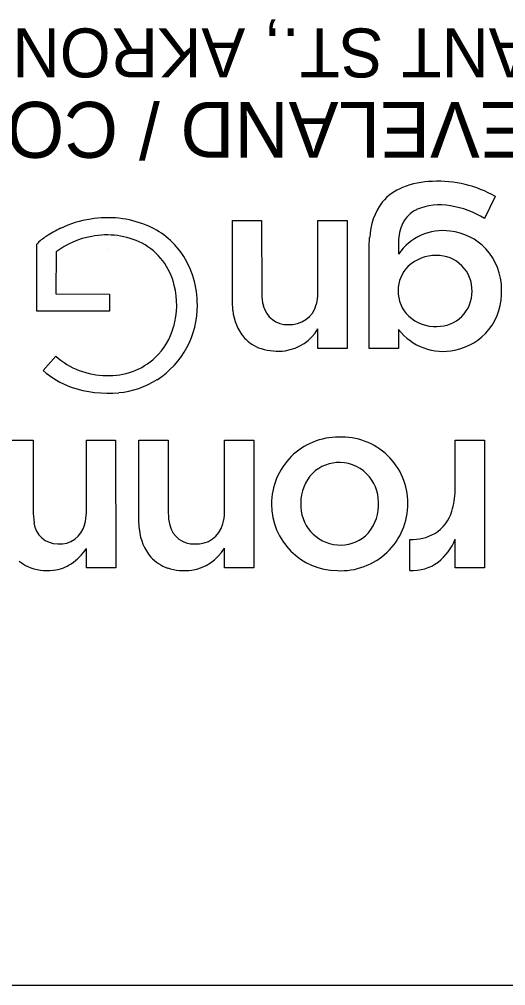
# Model space of a CAD drawing. Extents: x 2392589 to 2394670, y 184794 to 185659.
# Drawn here: x 2392957.49 to 2392967.39, y 185619.17 to 185638.86 of the extents above; entities that cross this region are included whole.
import ezdxf

# ---------------------------------------------------------------- set-up
doc = ezdxf.new("R2010")
doc.units = 0
doc.layers.add('MD_P_Surface_Asphalt_Concrete_Surface_Course', color=7, linetype='Continuous')
doc.layers.add('MD_P_Surface_Finished_Grade_Seeded', color=7, linetype='Continuous')

msp = doc.modelspace()

# ---------------------------------------------------------------- linework, layer by layer
at = {"layer": 'MD_P_Surface_Asphalt_Concrete_Surface_Course'}
for p, q in [((2392967.181, 185635.244), (2392966.96, 185634.797)), ((2392961.826, 185633.099), (2392961.826, 185634.756)), ((2392961.826, 185634.756), (2392962.422, 185634.756)), ((2392962.422, 185634.756), (2392962.423, 185633.269)), ((2392963.568, 185634.755), (2392964.164, 185634.756)), ((2392963.568, 185633.286), (2392963.568, 185634.755)), ((2392964.164, 185634.756), (2392964.166, 185632.15)), ((2392964.615, 185634.22), (2392964.622, 185634.411)), ((2392965.208, 185634.325), (2392965.207, 185634.07)), ((2392957.842, 185632.909), (2392957.841, 185634.276)), ((2392958.234, 185634.12), (2392958.231, 185633.262)), ((2392959.279, 185634.173), (2392959.279, 185634.173)), ((2392964.615, 185632.15), (2392964.615, 185634.22)), ((2392958.231, 185633.262), (2392959.324, 185633.259)), ((2392959.324, 185633.259), (2392959.324, 185632.909)), ((2392961.835, 185632.929), (2392961.826, 185633.099)), ((2392959.324, 185632.909), (2392957.842, 185632.909)), ((2392963.569, 185632.15), (2392963.568, 185632.552)), ((2392965.212, 185632.54), (2392965.212, 185632.15)), ((2392964.166, 185632.15), (2392963.569, 185632.15)), ((2392965.212, 185632.15), (2392964.615, 185632.15)), ((2392957.97, 185631.7), (2392958.231, 185631.995)), ((2392957.17, 185630.287), (2392957.766, 185630.287)), ((2392957.766, 185630.287), (2392957.766, 185628.79)), ((2392958.852, 185628.814), (2392958.852, 185630.287)), ((2392958.852, 185630.287), (2392959.448, 185630.287)), ((2392959.448, 185630.287), (2392959.449, 185627.681)), ((2392959.923, 185628.63), (2392959.923, 185630.287)), ((2392959.923, 185630.287), (2392960.519, 185630.287)), ((2392960.519, 185630.287), (2392960.52, 185628.8)), ((2392961.665, 185630.286), (2392962.26, 185630.287)), ((2392961.665, 185628.817), (2392961.665, 185630.286)), ((2392962.26, 185630.287), (2392962.262, 185627.681)), ((2392966.363, 185629.255), (2392966.365, 185630.287)), ((2392966.365, 185630.287), (2392966.961, 185630.286)), ((2392966.961, 185630.286), (2392966.961, 185627.681)), ((2392957.766, 185628.79), (2392957.785, 185628.601)), ((2392959.932, 185628.46), (2392959.923, 185628.63)), ((2392965.441, 185627.632), (2392965.441, 185628.263)), ((2392966.364, 185627.681), (2392966.364, 185628.267)), ((2392958.852, 185627.681), (2392958.852, 185628.076)), ((2392961.666, 185627.681), (2392961.665, 185628.083)), ((2392959.449, 185627.681), (2392958.852, 185627.681)), ((2392962.262, 185627.681), (2392961.666, 185627.681)), ((2392966.961, 185627.681), (2392966.364, 185627.681))]:
    msp.add_line(p, q, dxfattribs=at)
for points in [[(2392967.181, 185635.244), (2392966.96, 185634.797)], [(2392961.835, 185632.929), (2392961.826, 185633.099), (2392961.826, 185634.756), (2392962.422, 185634.756), (2392962.423, 185633.269)], [(2392963.568, 185633.286), (2392963.568, 185634.755), (2392964.164, 185634.756), (2392964.166, 185632.15)], [(2392965.212, 185632.54), (2392965.212, 185632.15), (2392964.615, 185632.15), (2392964.615, 185634.22), (2392964.622, 185634.411)], [(2392965.208, 185634.325), (2392965.207, 185634.07)], [(2392958.234, 185634.12), (2392958.231, 185633.262), (2392959.324, 185633.259), (2392959.324, 185632.909), (2392957.842, 185632.909), (2392957.841, 185634.276)], [(2392964.166, 185632.15), (2392963.569, 185632.15), (2392963.568, 185632.552)], [(2392957.97, 185631.7), (2392958.231, 185631.995)], [(2392957.169, 185628.816), (2392957.17, 185630.287), (2392957.766, 185630.287), (2392957.766, 185628.79), (2392957.785, 185628.601)], [(2392958.852, 185628.814), (2392958.852, 185630.287), (2392959.448, 185630.287), (2392959.449, 185627.681)], [(2392959.932, 185628.46), (2392959.923, 185628.63), (2392959.923, 185630.287), (2392960.519, 185630.287), (2392960.52, 185628.8)], [(2392961.665, 185628.817), (2392961.665, 185630.286), (2392962.26, 185630.287), (2392962.262, 185627.681)], [(2392966.363, 185629.255), (2392966.365, 185630.287), (2392966.961, 185630.286), (2392966.961, 185627.681)], [(2392965.441, 185627.632), (2392965.441, 185628.263)], [(2392966.961, 185627.681), (2392966.364, 185627.681), (2392966.364, 185628.267)], [(2392959.449, 185627.681), (2392958.852, 185627.681), (2392958.852, 185628.076)], [(2392962.262, 185627.681), (2392961.666, 185627.681), (2392961.665, 185628.083)]]:
    msp.add_lwpolyline(points, dxfattribs=at)
for centre, radius, start, end in [((2392965.937, 185633.786), 1.767, 91.1514, 111.3627), ((2392965.937, 185633.786), 1.767, 91.1514, 111.3627), ((2392966.031, 185633.28), 2.277, 59.6388, 93.26), ((2392966.031, 185633.28), 2.277, 59.6388, 93.26), ((2392965.672, 185634.476), 1.028, 111.6075, 140.5577), ((2392965.672, 185634.476), 1.028, 111.6075, 140.5577), ((2392965.922, 185634.354), 1.301, 143.4034, 177.4906), ((2392965.922, 185634.354), 1.301, 143.4034, 177.4906), ((2392965.848, 185634.425), 0.617, 116.2681, 153.803), ((2392965.848, 185634.425), 0.617, 116.2681, 153.803), ((2392966.049, 185633.886), 1.191, 79.3073, 113.4307), ((2392966.049, 185633.886), 1.191, 79.3073, 113.4307), ((2392966.012, 185633.32), 1.754, 57.3149, 81.5748), ((2392966.012, 185633.32), 1.754, 57.3149, 81.5748), ((2392959.282, 185632.58), 2.233, 98.8034, 115.3348), ((2392959.282, 185632.58), 2.233, 98.8034, 115.3348), ((2392959.284, 185632.685), 2.13, 68.2887, 99.2855), ((2392959.284, 185632.685), 2.13, 68.2887, 99.2855), ((2392966.134, 185634.306), 0.927, 155.0169, 178.8011), ((2392966.134, 185634.306), 0.927, 155.0169, 178.8011), ((2392959.276, 185632.591), 2.221, 115.3031, 123.9618), ((2392959.276, 185632.591), 2.221, 115.3031, 123.9618), ((2392959.446, 185633.14), 1.648, 35.0306, 67.6757), ((2392959.446, 185633.14), 1.648, 35.0306, 67.6757), ((2392966.114, 185633.457), 1.094, 82.1125, 145.923), ((2392966.114, 185633.457), 1.094, 82.1125, 145.923), ((2392966.138, 185633.37), 1.177, 43.742, 83.8554), ((2392966.138, 185633.37), 1.177, 43.742, 83.8554), ((2392958.492, 185633.672), 0.888, 120.9891, 137.161), ((2392958.492, 185633.672), 0.888, 120.9891, 137.161), ((2392959.26, 185632.75), 1.711, 100.0751, 126.8319), ((2392959.26, 185632.75), 1.711, 100.0751, 126.8319), ((2392959.268, 185632.857), 1.607, 63.4669, 101.0367), ((2392959.268, 185632.857), 1.607, 63.4669, 101.0367), ((2392959.37, 185633.146), 1.304, 12.8815, 61.8147), ((2392959.37, 185633.146), 1.304, 12.8815, 61.8147), ((2392966.099, 185633.363), 1.21, 359.6361, 42.7088), ((2392966.099, 185633.363), 1.21, 359.6361, 42.7088), ((2392959.284, 185633.058), 1.828, 359.3273, 34.1963), ((2392959.284, 185633.058), 1.828, 359.3273, 34.1963), ((2392965.959, 185633.246), 0.799, 88.5714, 133.5376), ((2392965.959, 185633.246), 0.799, 88.5714, 133.5376), ((2392965.999, 185633.336), 0.709, 358.2788, 91.5502), ((2392965.999, 185633.336), 0.709, 358.2788, 91.5502), ((2392965.887, 185633.335), 0.685, 134.2719, 180.4762), ((2392965.887, 185633.335), 0.685, 134.2719, 180.4762), ((2392959.029, 185633.036), 1.662, 344.4535, 13.9512), ((2392959.029, 185633.036), 1.662, 344.4535, 13.9512), ((2392965.894, 185633.311), 0.692, 178.473, 226.4256), ((2392965.894, 185633.311), 0.692, 178.473, 226.4256), ((2392966.005, 185633.302), 0.702, 268.8821, 1.0837), ((2392966.005, 185633.302), 0.702, 268.8821, 1.0837), ((2392966.057, 185633.299), 1.254, 322.4606, 2.5902), ((2392966.057, 185633.299), 1.254, 322.4606, 2.5902), ((2392963.344, 185633.263), 0.92, 179.6051, 195.3303), ((2392963.344, 185633.263), 0.92, 179.6051, 195.3303), ((2392962.725, 185633.278), 0.843, 344.0891, 0.5284), ((2392962.725, 185633.278), 0.843, 344.0891, 0.5284), ((2392959.33, 185633.015), 1.782, 302.7022, 0.714), ((2392959.33, 185633.015), 1.782, 302.7022, 0.714), ((2392962.829, 185633.016), 0.998, 184.9706, 220.2248), ((2392962.829, 185633.016), 0.998, 184.9706, 220.2248), ((2392962.941, 185633.138), 0.5, 193.6868, 272.214), ((2392962.941, 185633.138), 0.5, 193.6868, 272.214), ((2392963.003, 185633.189), 0.551, 265.5844, 345.1382), ((2392963.003, 185633.189), 0.551, 265.5844, 345.1382), ((2392965.959, 185633.401), 0.802, 227.4674, 272.3324), ((2392965.959, 185633.401), 0.802, 227.4674, 272.3324), ((2392959.277, 185632.982), 1.408, 314.0215, 343.88), ((2392959.277, 185632.982), 1.408, 314.0215, 343.88), ((2392962.754, 185633.047), 0.953, 278.9646, 328.6987), ((2392962.754, 185633.047), 0.953, 278.9646, 328.6987), ((2392966.117, 185633.231), 1.138, 217.3748, 282.2247), ((2392966.117, 185633.231), 1.138, 217.3748, 282.2247), ((2392966.14, 185633.265), 1.167, 280.7518, 321.2892), ((2392966.14, 185633.265), 1.167, 280.7518, 321.2892), ((2392962.662, 185632.911), 0.803, 222.2238, 251.6823), ((2392962.662, 185632.911), 0.803, 222.2238, 251.6823), ((2392962.751, 185633.216), 1.12, 252.274, 277.7917), ((2392962.751, 185633.216), 1.12, 252.274, 277.7917), ((2392959.263, 185633.152), 1.551, 228.258, 269.7006), ((2392959.263, 185633.152), 1.551, 228.258, 269.7006), ((2392959.333, 185632.935), 1.335, 266.6658, 313.6912), ((2392959.333, 185632.935), 1.335, 266.6658, 313.6912), ((2392959.242, 185633.205), 1.971, 229.7948, 249.137), ((2392959.242, 185633.205), 1.971, 229.7948, 249.137), ((2392959.286, 185633.547), 2.307, 251.1438, 275.6281), ((2392959.286, 185633.547), 2.307, 251.1438, 275.6281), ((2392959.339, 185633.04), 1.797, 275.5077, 302.0129), ((2392959.339, 185633.04), 1.797, 275.5077, 302.0129), ((2392963.985, 185628.984), 1.362, 89.5401, 180.2114), ((2392963.985, 185628.984), 1.362, 89.5401, 180.2114), ((2392964.052, 185628.997), 1.35, 0.0624, 92.3776), ((2392964.052, 185628.997), 1.35, 0.0624, 92.3776), ((2392963.995, 185629.064), 0.764, 87.8857, 134.159), ((2392963.995, 185629.064), 0.764, 87.8857, 134.159), ((2392964.016, 185629.062), 0.766, 38.2894, 89.4347), ((2392964.016, 185629.062), 0.766, 38.2894, 89.4347), ((2392964.079, 185629.013), 0.86, 135.8426, 180.9801), ((2392964.079, 185629.013), 0.86, 135.8426, 180.9801), ((2392963.921, 185628.992), 0.884, 356.5651, 38.0608), ((2392963.921, 185628.992), 0.884, 356.5651, 38.0608), ((2392964.949, 185629.266), 1.414, 342.4655, 359.573), ((2392964.949, 185629.266), 1.414, 342.4655, 359.573), ((2392963.971, 185628.975), 1.348, 179.8476, 269.6405), ((2392963.971, 185628.975), 1.348, 179.8476, 269.6405), ((2392964.027, 185628.957), 0.808, 177.0481, 265.5726), ((2392964.027, 185628.957), 0.808, 177.0481, 265.5726), ((2392964.038, 185628.989), 1.364, 266.8344, 0.4038), ((2392964.038, 185628.989), 1.364, 266.8344, 0.4038), ((2392957.976, 185628.811), 0.876, 343.6672, 0.1498), ((2392957.976, 185628.811), 0.876, 343.6672, 0.1498), ((2392961.44, 185628.794), 0.92, 179.6051, 195.3303), ((2392961.44, 185628.794), 0.92, 179.6051, 195.3303), ((2392960.822, 185628.809), 0.843, 344.0891, 0.5284), ((2392960.822, 185628.809), 0.843, 344.0891, 0.5284), ((2392963.958, 185628.956), 0.846, 313.0999, 358.8089), ((2392963.958, 185628.956), 0.846, 313.0999, 358.8089), ((2392965.517, 185629.075), 0.816, 301.9447, 343.2028), ((2392965.517, 185629.075), 0.816, 301.9447, 343.2028), ((2392958.268, 185628.657), 0.487, 186.5532, 269.949), ((2392958.268, 185628.657), 0.487, 186.5532, 269.949), ((2392958.307, 185628.694), 0.526, 265.722, 345.7863), ((2392958.307, 185628.694), 0.526, 265.722, 345.7863), ((2392960.926, 185628.547), 0.998, 184.9706, 220.2248), ((2392960.926, 185628.547), 0.998, 184.9706, 220.2248), ((2392961.038, 185628.669), 0.5, 193.6868, 272.214), ((2392961.038, 185628.669), 0.5, 193.6868, 272.214), ((2392961.1, 185628.72), 0.551, 265.5844, 345.1382), ((2392961.1, 185628.72), 0.551, 265.5844, 345.1382), ((2392964.029, 185628.918), 0.77, 265.1538, 311.1471), ((2392964.029, 185628.918), 0.77, 265.1538, 311.1471), ((2392965.49, 185629.19), 0.928, 266.9688, 299.6064), ((2392965.49, 185629.19), 0.928, 266.9688, 299.6064), ((2392965.336, 185628.666), 1.102, 308.0981, 338.7907), ((2392965.336, 185628.666), 1.102, 308.0981, 338.7907), ((2392957.864, 185628.75), 1.196, 304.7043, 325.6872), ((2392957.864, 185628.75), 1.196, 304.7043, 325.6872), ((2392960.851, 185628.578), 0.953, 278.9646, 328.6987), ((2392960.851, 185628.578), 0.953, 278.9646, 328.6987), ((2392957.989, 185628.411), 0.775, 229.5245, 244.847), ((2392957.989, 185628.411), 0.775, 229.5245, 244.847), ((2392960.759, 185628.442), 0.803, 222.2238, 251.6823), ((2392960.759, 185628.442), 0.803, 222.2238, 251.6823), ((2392965.503, 185628.496), 0.866, 265.8731, 306.3475), ((2392965.503, 185628.496), 0.866, 265.8731, 306.3475), ((2392958.055, 185628.601), 0.975, 246.0638, 277.3493), ((2392958.055, 185628.601), 0.975, 246.0638, 277.3493), ((2392958.085, 185628.465), 0.836, 276.5579, 303.3885), ((2392958.085, 185628.465), 0.836, 276.5579, 303.3885), ((2392960.848, 185628.747), 1.12, 252.274, 277.7917), ((2392960.848, 185628.747), 1.12, 252.274, 277.7917)]:
    msp.add_arc(centre, radius, start, end, dxfattribs=at)
at = {"layer": 'MD_P_Surface_Finished_Grade_Seeded'}
msp.add_line((2393019.279, 185619.173), (2392599.279, 185619.173), dxfattribs=at)

# ---------------------------------------------------------------- texts
at = {"layer": 'MD_P_Surface_Asphalt_Concrete_Surface_Course'}
for s, height, p in [('450 GRANT ST., AKRON, OH  44311', 0.99692, (2392972.532, 185638.67)), ('AKRON / CLEVELAND / COLUMBUS', 1.13938, (2392976.519, 185637.175))]:
    msp.add_text(s, height=height, rotation=180, dxfattribs=at).set_placement(p)

doc.saveas('drawing.dxf')
